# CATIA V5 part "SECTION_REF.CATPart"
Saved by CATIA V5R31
Part number: SECTION_REF
Bounding box of the stored display mesh (mm): x 0 to 0, y -140 to 110, z -90 to 60
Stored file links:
  \\solize.local\damia\dept\DDE_Design\10_order\2305701_JAMA_変換検証STEP3_お手本モデル作成\work\03_東洋電装_スイッチ\10_CATIA_V5\SECTION_REF.CATPart
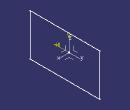
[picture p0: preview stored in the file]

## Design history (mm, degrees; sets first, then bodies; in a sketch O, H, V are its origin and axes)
AxisSystem1: origin (0, 0, 0), X (1, 0, 0), Y (0, 1, 0), Z (0, 0, 1)
Set1
  Sketch1 on YZ plane of AxisSystem1, origin (0, 0, 0), H (0, -1, 0), V (0, 0, 1)
    line L1 (-110, 60) -> (140, 60)
    line L2 (140, 60) -> (140, -90)
    line L3 (140, -90) -> (-110, -90)
    line L4 (-110, -90) -> (-110, 60)
    distance L4 L2 = 250
    distance L1 L3 = 150
    distance L1 H = 60
    distance V L4 = 110
    horizontal: L1 H, L3 H
    vertical: L2 V, L4 V
Body1 (main body)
